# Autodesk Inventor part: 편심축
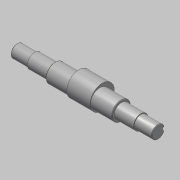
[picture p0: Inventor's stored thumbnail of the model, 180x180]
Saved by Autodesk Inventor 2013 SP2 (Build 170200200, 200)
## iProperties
Created: 2015-10
Part Number: 편심축
Document SubType Name: Modeling
Designer: mdu
Density: 1 g/cm^3
Material: 강철, 연강
Mass: 168.947 g
Surface Area: 248.524 cm^2
Volume: 168.947 cm^3
Author: mdu
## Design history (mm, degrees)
sketch "스케치1"
  geometry: L1 (-20.5, -41.331)-(-20.5, 32.669) reference; L2 (7.5, -30.031)-(7.5, 21.369) reference; L3 (135.5, -30.331)-(135.5, 21.669) reference; L4 (121.5, 21.369)-(121.5, -30.031) reference; L5 (184.5, -4.331)-(-57.5, -4.331); L6 (184.5, -4.331)-(184.5, 6.669); L7 (154.5, 8.169)-(121.5, 8.169); L8 (121.5, 8.169)-(121.5, 11.669); L9 (121.5, 11.669)-(7.5, 11.669); L10 (7.5, 11.669)-(7.5, 8.169); L11 (7.5, 8.169)-(-27.5, 8.169); L12 (-27.5, 8.169)-(-27.5, 6.669); L13 (-27.5, 6.669)-(-57.5, 6.669); L14 (-57.5, 6.669)-(-57.5, -4.331); L15 (154.5, 8.169)-(154.5, 6.669); L16 (154.5, 6.669)-(184.5, 6.669); C1 r 32.5 at (64.5, -4.331) reference; 1 further point
  constraints: 24 end point, 8 perpendicular, 5 point on line, 3 parallel, 2 collinear
  dimensions: "d1" = 25 diameter of L11 L5; "d2" = 32 diameter of L9 L5; "d3" = 22 diameter of L13 L5; "d4" = 35 distance of L10.end L11.end; "d5" = 30 distance of L12.end L13.end; "d15" = 33 distance of L7.start L7.end; "d26" = 30 distance of L15.end L6.end
revolve "회전1" sketch "스케치1" stored, may be unused: angle "d6" = 90 deg
node "작업 평면1"
sketch "스케치2"
  geometry: C1 r 16 at (0, 0) reference; C2 r 20.75 at (0, 4)
  constraints: 1 centre point, 1 vertical alignment
  dimensions: "d34" = 4 distance of C2.centre C1.centre; "d35" = 41.5 diameter of C2
extrude "돌출1" join sketch "스케치2" stored distance "d9" = 40; taper "d10" = 0 deg
chamfer "모따기1" distance "d11" = 1; stored, may be unused: second distance "d12" = 2, angle "d13" = 45 deg
node "작업 평면2"
sketch "스케치3"
  geometry: L1 (-15, -10)-(-15, 10) reference; L2 (-15, 3)-(0, 3); L3 (0, -3)-(-15, -3); A1 r 3 centre (0, 0) between (0, -3) and (0, 3); 2 further points
  constraints: 4 end point, 2 perpendicular, 2 point on circle, 2 point on line, 2 tangent, 1 centre point, 1 horizontal alignment, 1 midpoint
  dimensions: "d16" = 18 dimension on A1 L1; "d17" = 6 distance between parallel lines of L3 L2
extrude "돌출2" cut sketch "스케치3" distance "d18" = 3.5; taper "d19" = 0 deg
node "작업 평면3"
node "솔리드1"
mirror "대칭1"
node "참조1"
node "참조2"
node "참조3"
node "참조4"
node "참조5"
other parameters: "d30" = 35
